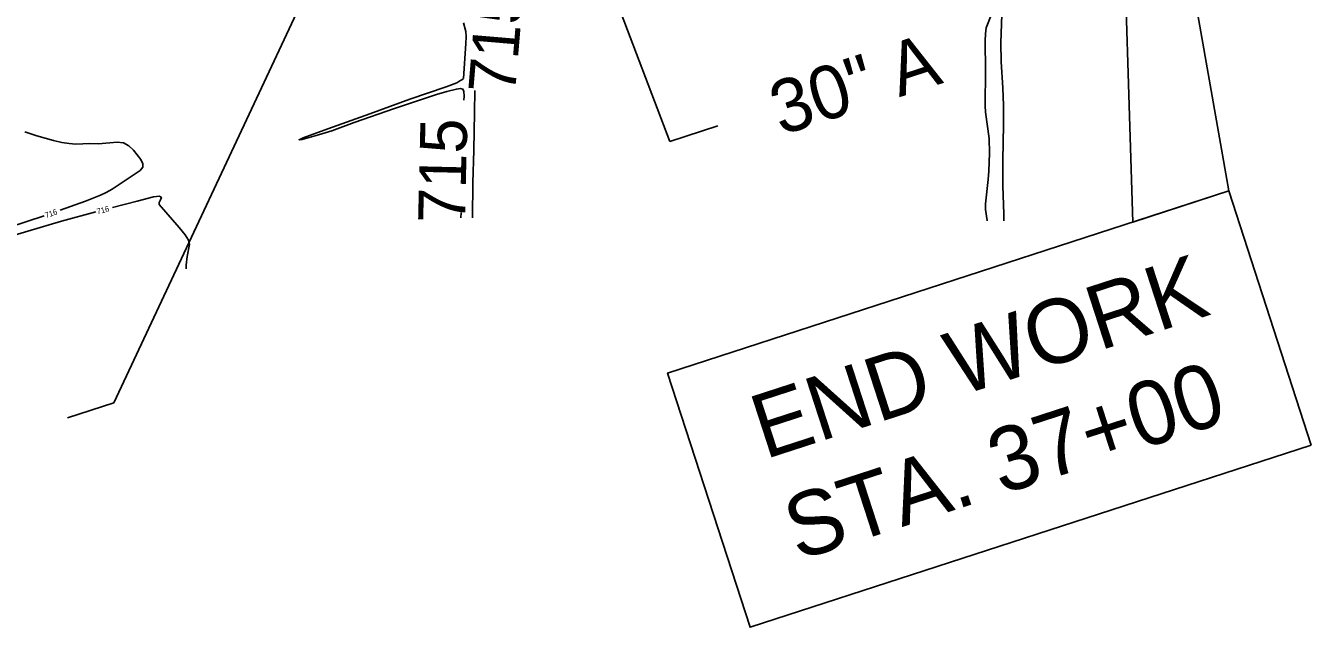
# Model space of a CAD drawing. Extents: x -468563856 to 36492962, y -306094093 to 11899197.
# Drawn here: x 1821405 to 1822310, y 530377 to 530800 of the extents above; entities that cross this region are included whole.
import ezdxf

# ---------------------------------------------------------------- set-up
doc = ezdxf.new("R2010")
doc.units = 0
for name, color, linetype in [('DT_X_Contour_Minor', 7, 'Continuous'), ('Level 19', 7, 'Continuous'), ('Level 40', 7, 'Continuous'), ('SH_Text', 7, 'Continuous')]:
    doc.layers.add(name, color=color, linetype=linetype)

msp = doc.modelspace()

# ---------------------------------------------------------------- linework, layer by layer
at = {"layer": 'DT_X_Contour_Minor'}
for points in [[(1822093.74, 530662.91), (1822093.72, 530667.68), (1822092.94, 530687.66), (1822092.94, 530705.62), (1822093.44, 530730.52), (1822093.39, 530744.21), (1822092.86, 530756.67), (1822091.78, 530774.92), (1822091.61, 530788.25), (1822092.54, 530814.67), (1822093.12, 530827.67), (1822093.27, 530833.18), (1822092.53, 530836.49), (1822092.07, 530841.2), (1822092.67, 530848.2), (1822092.48, 530848.25), (1822089.97, 530847.57), (1822079.96, 530844.35), (1822076.48, 530843.73), (1822068.89, 530844.24), (1822043, 530845.11), (1822014.05, 530846.85), (1821990.08, 530847.71)], [(1822080.47, 530835.95), (1822081.38, 530835.64), (1822082.32, 530835.02), (1822084.78, 530831.35), (1822085.14, 530829.87), (1822086.16, 530818.85), (1822086.26, 530815.4), (1822086.04, 530812.13), (1822085.31, 530808.99), (1822081.28, 530798.83), (1822080.66, 530794.48), (1822080.52, 530789.64), (1822080.85, 530768.77), (1822080.43, 530743.97), (1822080.83, 530739.36), (1822083.44, 530720.8), (1822083.52, 530710.51), (1822083.16, 530697.98), (1822082.72, 530692.03), (1822080.65, 530674.88), (1822080.8, 530671), (1822081.86, 530663.1), (1822081.9, 530662.98)], [(1821713.19, 530802.21), (1821714.82, 530796.11), (1821714.9, 530792.37), (1821714.67, 530787.72), (1821713.1, 530763.15), (1821711.89, 530762.3), (1821710.63, 530761.39), (1821708.41, 530760.18), (1821700.9, 530757.22), (1821675.4, 530748.59), (1821647.21, 530738.2), (1821617.6, 530727.73), (1821600.3, 530721.35), (1821597.35, 530720), (1821599.51, 530720.29), (1821611.01, 530723.38), (1821620.45, 530726.38), (1821636.17, 530732.1), (1821664.53, 530742.09), (1821694.19, 530751.92), (1821701.37, 530753.92), (1821708.11, 530755.68), (1821711.04, 530756.06), (1821712.75, 530755.59), (1821713.44, 530753.93), (1821713.52, 530750.74), (1821713.39, 530747.78)], [(1821719.5, 530665.08), (1821719.72, 530689.64), (1821720.3, 530712.57), (1821720.8, 530739.22), (1821721.06, 530754.58)], [(1821429.09, 530670.36), (1821446.98, 530676.74), (1821457.35, 530680.93), (1821461.52, 530682.92), (1821465.78, 530685.32), (1821485.36, 530698.39), (1821487.33, 530700.65), (1821487.32, 530703.16), (1821485.77, 530706.01), (1821480.63, 530712.69), (1821477.49, 530715.82), (1821473.71, 530717.89), (1821469.2, 530718.42), (1821456.12, 530717.15), (1821449.98, 530717.36), (1821439.99, 530716.93), (1821435.44, 530717.3), (1821430.2, 530718.13), (1821424.45, 530719.38), (1821412.62, 530722.74), (1821404.22, 530725.61)], [(1821517.71, 530629.03), (1821517.69, 530631.79), (1821518.54, 530637.84), (1821520.05, 530646.27), (1821519.4, 530649.27), (1821517.04, 530653.02), (1821512.74, 530658.34), (1821498.71, 530674.41), (1821498.81, 530675.92), (1821499.79, 530677.71), (1821500.37, 530679.37), (1821499.05, 530680.19), (1821494.89, 530679.72), (1821483.29, 530676.86), (1821465.82, 530672.25)], [(1821088.22, 530562.57), (1821107.26, 530568.98), (1821131.38, 530576.94), (1821160.6, 530586.23), (1821184.85, 530593.8), (1821214.28, 530602.95), (1821239.35, 530611.09), (1821264.7, 530619.27), (1821295.76, 530629.14), (1821309.38, 530633.71), (1821329.13, 530640.9), (1821336.97, 530642.85), (1821364.46, 530649.26), (1821376.91, 530652.52), (1821384.4, 530655.17), (1821392.57, 530658.28), (1821417.76, 530666.41)], [(1821454.22, 530669.16), (1821429.94, 530662.62), (1821406.37, 530655.57), (1821388.11, 530650.23)], [(1821711.4, 530668.82), (1821711.4, 530668.71), (1821711.34, 530665.13)]]:
    msp.add_lwpolyline(points, dxfattribs=at)
at = {"layer": 'Level 40'}
for p, q in [((1821466.95, 530534.8), (1821740.2, 531118.06)), ((1821858.36, 530718.77), (1821771.32, 530948.98)), ((1821858.36, 530718.77), (1821892.33, 530729.8)), ((1821434.24, 530524.18), (1821466.95, 530534.8))]:
    msp.add_line(p, q, dxfattribs=at)
at = {"layer": 'SH_Text'}
for points in [[(1822184.44, 530662.05), (1822168.94, 531156.04), (1822252.12, 530684.02)], [(1822310.21, 530505.1), (1821914.96, 530376.78), (1821856.87, 530555.7), (1822252.12, 530684.02)]]:
    msp.add_lwpolyline(points, close=True, dxfattribs=at)

# ---------------------------------------------------------------- texts
at = {"layer": 'Level 19'}
for s, height, rotation, p in [('715', 33, 85.18736, (1821749.29, 530751.55)), ('715', 33, 88.65949, (1821714.1, 530661.02)), ('716', 4, 19.60662, (1821419.07, 530664.67)), ('716', 4, 15.07452, (1821455.37, 530667.4))]:
    msp.add_text(s, height=height, rotation=rotation, dxfattribs=at).set_placement(p)
at = {"layer": 'Level 40'}
msp.add_text('30" A', height=37.5, rotation=17.9864, dxfattribs=at).set_placement((1821936.71, 530722.83))
at = {"layer": 'SH_Text'}
for s, p in [('END WORK', (1821925.32, 530494.87)), ('STA. 37+00', (1821948.52, 530423.42))]:
    msp.add_text(s, height=45.072, rotation=17.9864, dxfattribs=at).set_placement(p)

doc.saveas('drawing.dxf')
